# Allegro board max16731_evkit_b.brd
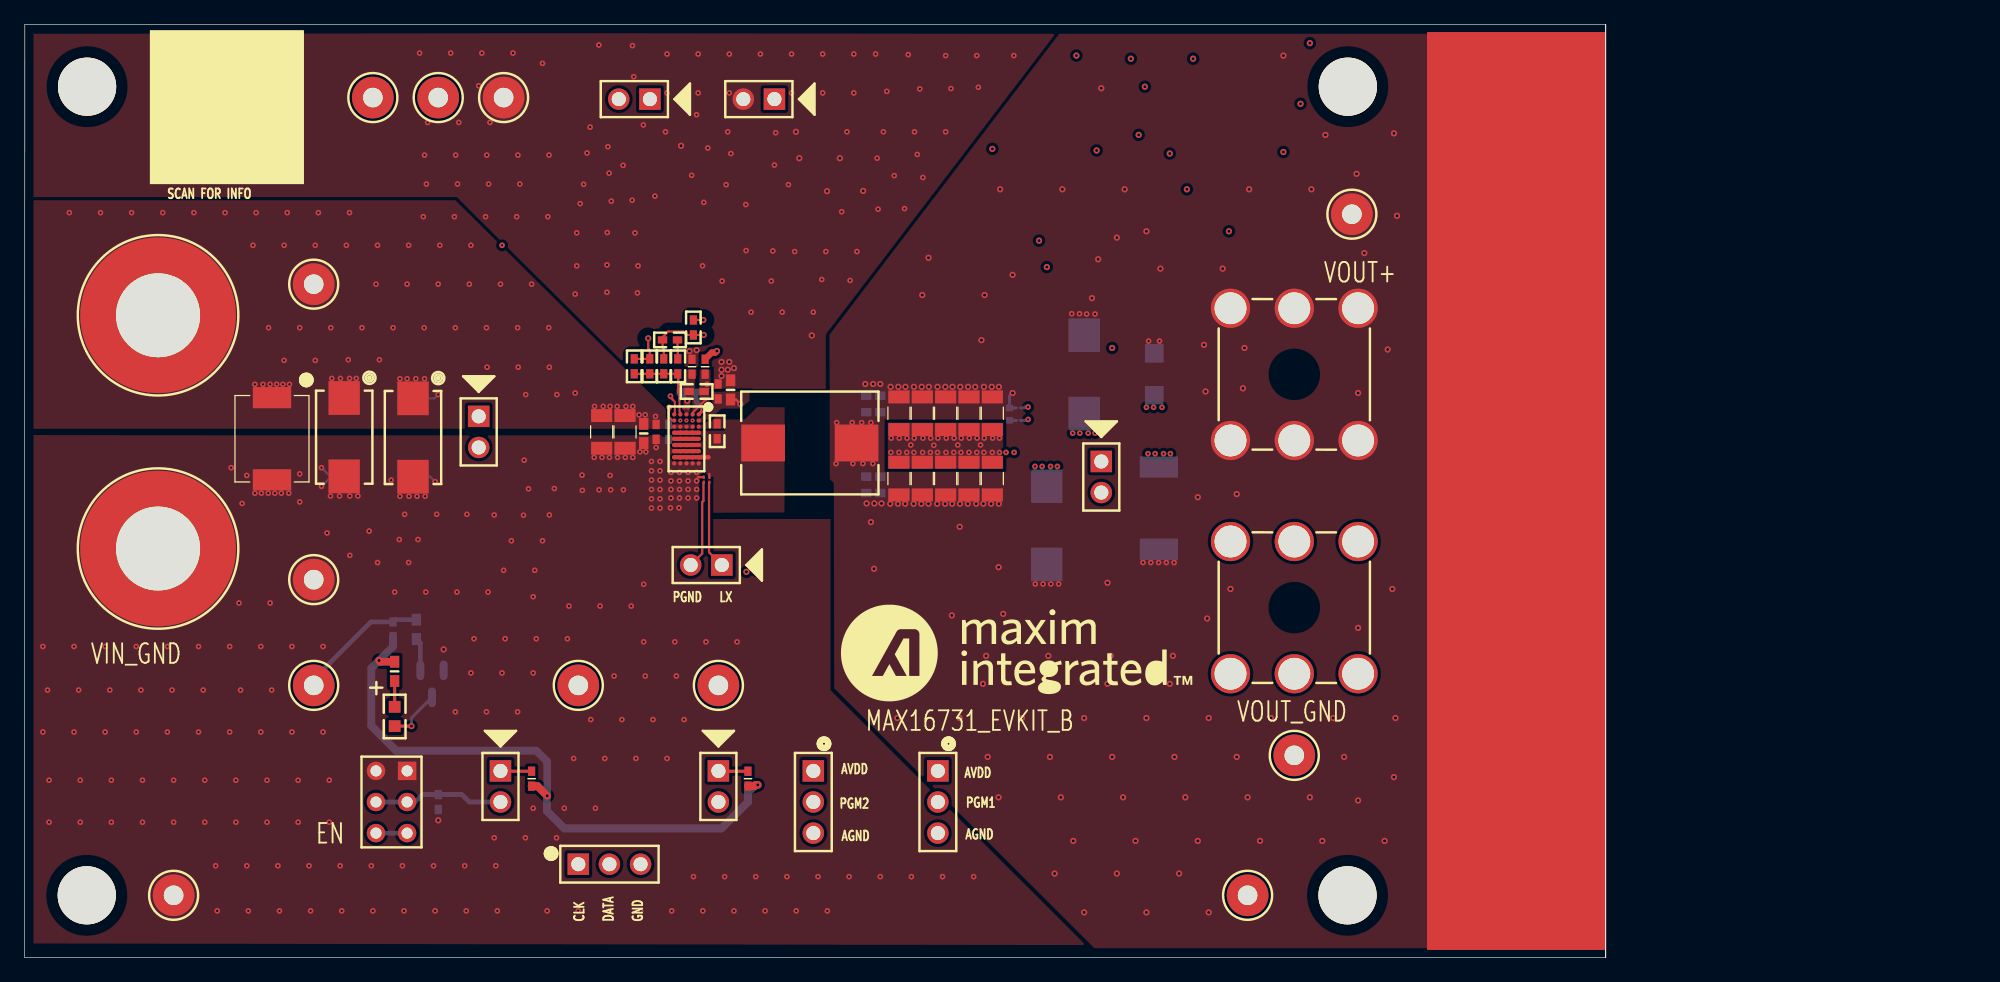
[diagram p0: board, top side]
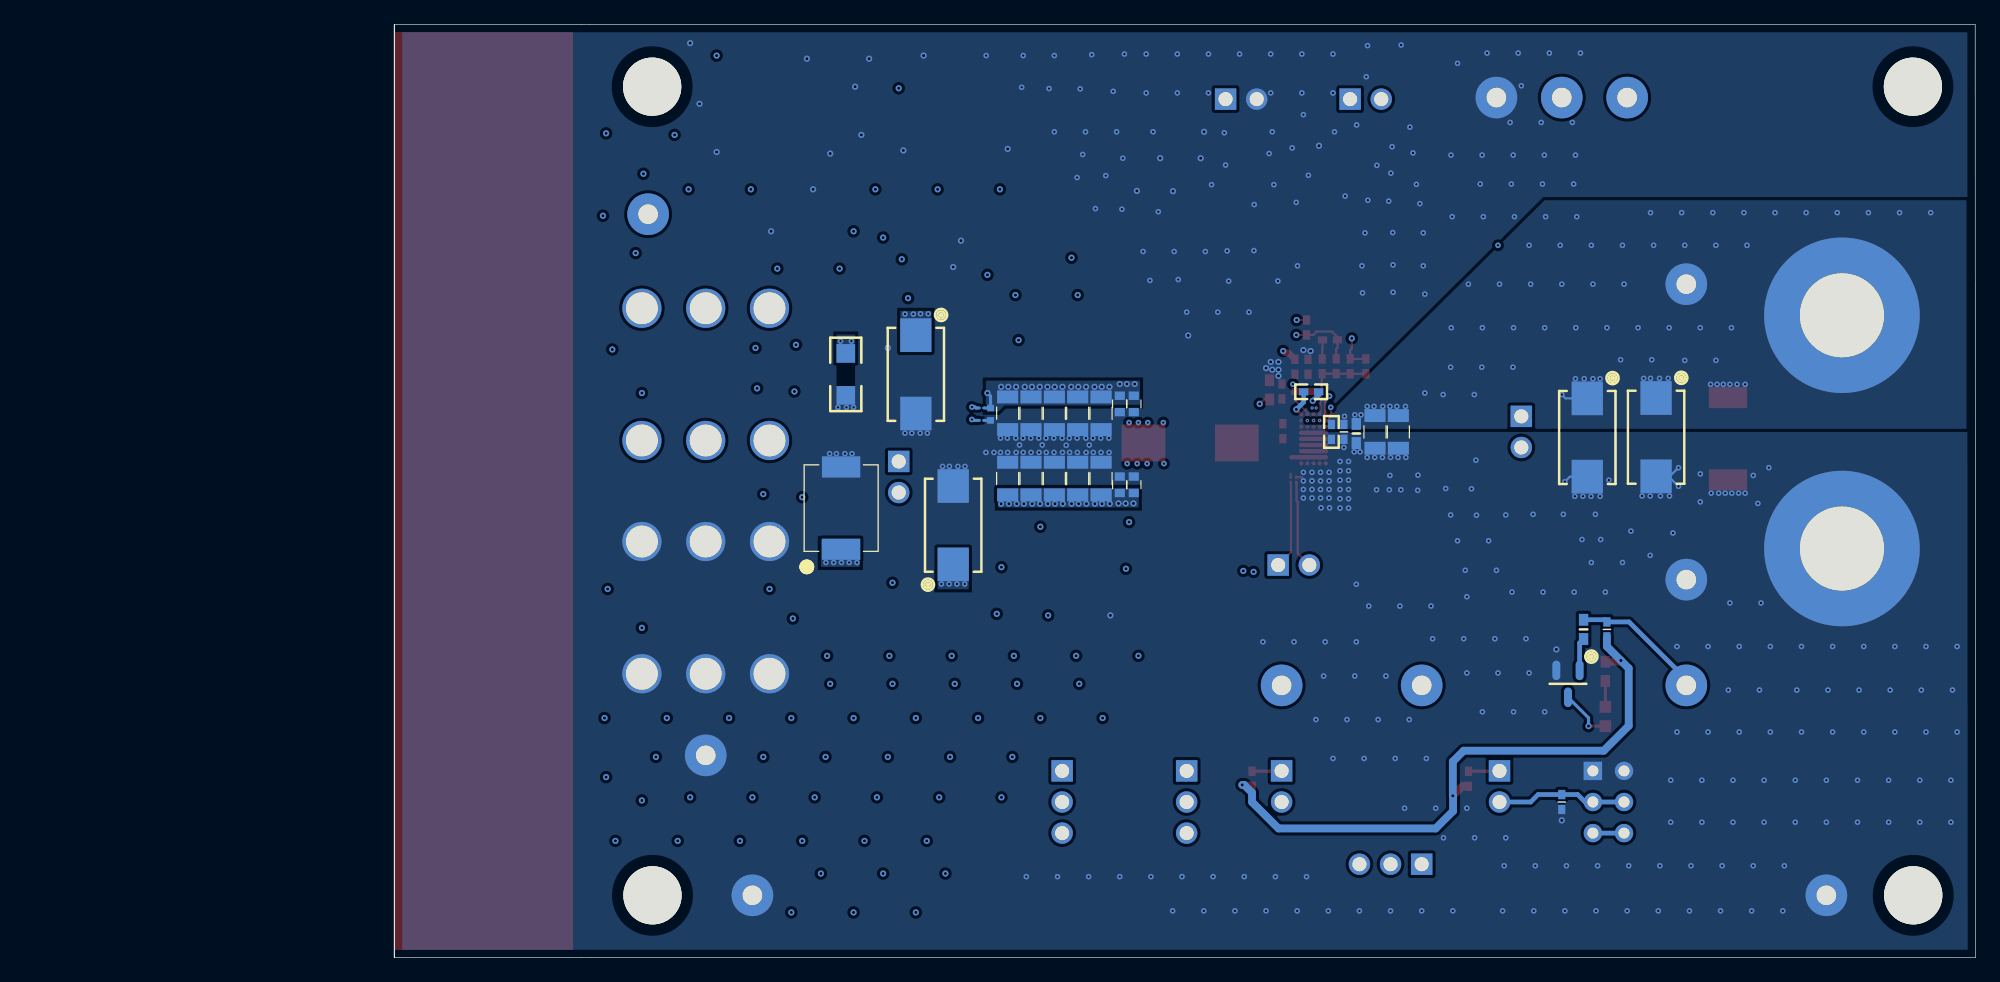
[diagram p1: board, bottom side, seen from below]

Outline 129.01 x 76.2 mm; copper layers: TOP, L2_PGND, L3_SIG_AGND, L4_SIG, L5_PGND, BOTTOM. Coordinates in mm from the lower left corner of the outline.
Outline path: 0,0 0.03,76.2 129.01,76.2 129.01,0 0,0

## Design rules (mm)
constraint set DEFAULT: min track width 0.178

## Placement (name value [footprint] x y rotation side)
C1  4.7UF  [0603]  57.61 46.36 270 top
C2  22UF  [1206]  49 42.93 90 top
C3  100UF  [1206]  78.97 39.12 270 bottom
C4  0.1UF  [0402]  56.59 46.23 270 top
C5  100UF  [1206]  73.25 39.12 270 bottom
C6  1UF  [0402]  54.84 46.23 0 top
C7  100UF  [1206]  75.16 44.45 90 bottom
C8  100UF  [1206]  73.25 44.45 90 bottom
C9  100UF  [1206]  73.25 44.45 90 top
C10  0.47UF  [0402]  56.52 42.98 90 top
C11  100UF  [1206]  73.25 39.12 270 top
C13  100UF  [1206]  71.35 44.45 90 top
C14  1UF  [0603]  50.52 42.8 90 top
C16  100UF  [1206]  71.35 39.12 270 top
C17  100PF  [0402]  49.75 48.28 270 top
C20  22UF  [1206]  47.09 42.93 90 top
C21  22UF  [1206]  49 42.93 90 bottom
C23  0.01UF  [0402]  52.67 50.44 0 top
C24  1UF  [0603]  50.52 42.8 90 bottom
C26  1000PF  [0402]  33.76 12.7 270 bottom
C27  4700PF  [0402]  52.55 42.93 90 bottom
C28  4700PF  [0402]  51.54 42.93 90 bottom
C29  0.1UF  [0402]  51.54 42.93 90 top
C30  22UF  [1206]  47.09 42.93 90 bottom
C31  470UF  [CAPMP7343X430M]  86.46 47.63 270 bottom
C32  100UF  [CAPMP7343X430M]  31.67 42.47 270 bottom
C33  100UF  [1206]  78.97 44.45 90 bottom
C34  100UF  [1206]  77.06 39.12 270 bottom
C35  100UF  [1206]  75.16 39.12 270 bottom
C36  100UF  [CAPMP7343X430M]  31.7 42.47 270 top
C37  100UF  [CAPMP7343X430M]  26.06 42.49 270 bottom
C39  100UF  [CAPMP7343X430M]  26.09 42.49 270 top
C40  470UF  [CAPMP7343X430M]  83.41 35.31 90 bottom
C41  47UF  [1206]  77.06 39.12 90 top
C43  47UF  [1206]  77.06 44.45 270 top
C44  47UF  [1206]  78.97 39.12 90 top
C46  100UF  [1206]  77.06 44.45 90 bottom
C47  0.1UF  [0402#2]  80.37 44.37 270 bottom
C48  100UF  [1206]  71.35 39.12 270 bottom
C49  47UF  [1206]  78.97 44.45 270 top
C50  100UF  [1206]  71.35 44.45 90 bottom
C51  10UF  [0603#2]  69.82 38.61 90 bottom
C52  10UF  [0603#2]  69.82 45.21 270 bottom
C53  10UF  [0603#2]  68.68 38.61 90 bottom
C54  100UF  [1206]  75.16 39.12 270 top
C55  100UF  [1206]  75.16 44.45 90 top
C72  10UF  [0603#2]  68.68 45.21 270 bottom
D1  MBRS540T3  [SOD9962X245M]  20.19 42.37 270 top
D3  MBRS540T3  [SOD9962X245M]  92.56 36.7 90 bottom
DS1  LGL29K-G2J1-24-Z  [LED_SMT160X080]  30.2 19.69 270 top
J1  PEC03SAAN  [SULLINS_PXC03SAAN]  74.52 15.24 270 top
J2  TSW-101-22-L-D  [SMTC_TSW-101-22-X-D]  61.19 70.1 90 top
J3  TSW-101-22-L-D  [SMTC_TSW-101-22-X-D]  51.03 70.1 90 top
J4  PEC03SAAN  [SULLINS_PXC03SAAN]  64.36 15.24 270 top
J5  6095  [KEYSTONE_6095]  10.9 52.45 0 top
J6  TSW-101-22-L-D  [SMTC_TSW-101-22-X-D]  38.84 15.24 180 top
J7  TSW-101-22-L-D  [SMTC_TSW-101-22-X-D]  56.62 15.24 180 top
J8  6095  [KEYSTONE_6095]  10.9 33.4 0 top
J9  PEC03SAAN  [SULLINS_PXC03SAAN]  45.19 7.62 0 top
J10  TSW-101-22-L-D  [SMTC_TSW-101-22-X-D]  37.06 44.2 180 top
J12  FINGERS_EVAL_NS  [EK_FINGERS_EVAL_NS]  121.72 38.1 90 top
J13  TSW-101-22-L-D  [SMTC_TSW-101-22-X-D]  56.9 32.05 90 top
J19  TSW-101-22-L-D  [SMTC_TSW-101-22-X-D]  87.86 40.51 180 top
L1  220NH  [IND_FP1008R5]  64.08 42.02 0 top
MH1  9032  [KEYS_9032]  5.11 71.12 180 bottom
MH2  9032  [KEYS_9032]  5.08 5.08 180 bottom
MH3  9032  [KEYS_9032]  107.98 71.12 180 bottom
MH4  9032  [KEYS_9032]  107.95 5.08 180 bottom
NOREF  -  []  0 0 90 top
NOREF#2  -  []  54.08 168.91 0 top
NOREF#3  -  []  0 0 0 top
NOREF#4  -  []  -10.69 -44.45 0 top
NOREF#5  -  []  10.23 63.16 0 top
NOREF#6  -  []  -17.04 -57.15 0 top
NOREF#7  -  []  70.59 24.77 0 top
NOREF#8  -  []  163.3 35.56 0 top
NOREF#9  -  []  -17.04 -57.15 180 bottom
Q1  BSS138  [SOT95P237X112-3M]  33.25 22.35 270 bottom
R1  4.7  [0402]  55.53 48.25 270 top
R2  95.3  [0402]  54.2 46.2 0 bottom
R4  100  [1206#2]  92.18 47.63 270 bottom
R9  3K  [0402]  51.02 48.28 90 top
R11  0  [0402]  54.47 48.25 270 top
R13  3K  [0402]  52.16 48.28 90 top
R14  10  [0402]  54.57 51.46 90 top
R16  3K  [0402]  41.38 14.61 270 top
R17  3K  [0402]  59.03 14.61 270 top
R19  0  [0402]  53.3 48.28 270 top
R41  20K  [0402]  30.07 26.8 270 bottom
R42  100  [0603]  31.98 26.8 270 bottom
R51  210  [0603]  30.2 23.37 270 top
ST1  7808  [KEYSTONE_7808]  103.61 47.63 270 top
ST2  7808  [KEYSTONE_7808]  103.61 28.58 270 top
SU3  SX1100-B  [EVKIT_SHUNT]  103.48 79.08 0 top
SW1  -  [SW_GT21MCBE]  29.95 12.7 180 top
TP1  N/A  [KEYS_5011]  39.09 70.23 0 top
TP2  N/A  [KEYS_5011]  12.17 5.08 0 top
TP4  N/A  [KEYS_5010]  23.6 54.99 0 top
TP6  N/A  [KEYS_5126]  56.62 22.23 0 top
TP7  N/A  [KEYS_5011]  23.6 30.86 0 top
TP8  N/A  [KEYS_5010]  108.31 60.71 0 top
TP9  N/A  [KEYS_5011]  99.8 5.08 90 top
TP11  N/A  [KEYS_5011]  103.61 16.51 0 top
TP13  N/A  [KEYS_5012]  28.42 70.23 90 top
TP14  N/A  [KEYS_5012]  33.76 70.23 90 top
TP29  N/A  [KEYS_5126]  45.19 22.23 90 top
TP30  N/A  [KEYS_5126]  23.6 22.23 90 top
U1  MAX16731  [MAXIM_21-100425_SMD]  54.01 42.36 270 top
Y1  CONN_SENSE_POINT  [EK_CONN_SENSE_POINT]  81.1 43.87 0 bottom
Y2  CONN_SENSE_POINT  [EK_CONN_SENSE_POINT]  81.1 44.88 0 bottom
Y12  CONN_SENSE_POINT  [EK_CONN_SENSE_POINT]  55.42 39.01 90 top
Y15  CONN_SENSE_POINT  [EK_CONN_SENSE_POINT]  55.88 39.01 90 top

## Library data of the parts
C1 = CAP_NP: alternate symbols: 0603_NOSILK,CAPC1608X90L,CAP0603-NOT_FOR_TEST; part number: CAP_NP_0603CAP-0603,4.7UF,20-004U7-R1
C2 C20 C21 C30 = CAP_NP: alternate symbols: CAPC3216X90L; part number: CAP_NP_1206CAP-1206,22UF,20-0022U-EA83
C3 C5 C7-C9 C11 C13 C16 C33-C35 C46 C48 C50 C54 C55 = CAP_NP: alternate symbols: CAPC3216X90L; part number: CAP_NP_1206CAP-1206,100UF,EC111000002982
C4 = CAP_NP: alternate symbols: 0402_NOSILK,CAPC1005X50L; part number: CAP_NP_0402CAP-0402,0.1UF,20-000U1-19A
C6 = CAP_NP: alternate symbols: 0402_NOSILK,CAPC1005X50L,CAP0402-NOT_FOR_TEST; part number: CAP_NP_0402CAP-0402,1UF,20-0001U-19A
C10 = CAP_NP: alternate symbols: 0402_NOSILK,CAPC1005X50L,CAP0402-NOT_FOR_TEST; part number: CAP_NP_0402CAP-0402,0.47UF,20-00U47-CA50
C14 C24 = CAP_NP: alternate symbols: 0603_NOSILK,CAPC1608X90L,CAP0603-NOT_FOR_TEST; part number: CAP_NP_0603CAP-0603,1UF,20-0001U-P6
C17 = CAP_NP: alternate symbols: 0402_NOSILK,CAPC1005X50L,CAP0402-NOT_FOR_TEST; part number: CAP_NP_0402CAP-0402,100PF,EC111000001552
C23 = CAP_NP: alternate symbols: 0402_NOSILK,CAPC1005X50L,CAP0402-NOT_FOR_TEST; part number: CAP_NP_0402CAP-0402,0.01UF,20-00U01-B16
C26 = CAP_NP: alternate symbols: 0402_NOSILK,CAPC1005X50L; part number: CAP_NP_0402CAP-0402,1000PF,20-1000P-E7
C27 C28 = CAP_NP: alternate symbols: 0402_NOSILK,CAPC1005X50L; part number: CAP_NP_0402CAP-0402,4700PF,20-4700P-12
C29 C47 = CAP_NP: alternate symbols: 0402_NOSILK,CAPC1005X50L,CAP0402-NOT_FOR_TEST; part number: CAP_NP_0402CAP-0402,0.1UF,20-000U1-B68
C31 C40 = CAP_POL: part number: CAP_POL_7343CAP-CAPMP7343X430M,470UF,20-0470U-N2
C32 C36 C37 C39 = CAP_POL: part number: CAP_POL_7343CAP-CAPMP7343X430M,100UF,20-0100U-I9A
C41 C43 C44 C49 = CAP_NP: alternate symbols: CAPC3216X90L; part number: CAP_NP_1206CAP-1206,47UF,ECM1107
C51-C53 C72 = CAP_NP: alternate symbols: 0603_NOSILK,CAPC1608X90L; part number: CAP_NP_0603CAP-0603,10UF,20-0010U-CA02
D1 D3 = DIO_SCHOTTKY: alternate symbols: SOD7958X245L; part number: DIO_SCHOTTKY_SMC_CASE403-03-SOD9962X245M,MBRS540T3,30-MBRS540T3-00
DS1 = LED: alternate symbols: LED_SMT160X080_ALT; part number: LED_SMT160X080-LED_SMT160X080,LGL29K-G2J1-24-Z,30-LGL29KG2J124Z-00
J1 J4 J9 = HEADER_3P: alternate symbols: SULLINS_PXC03SL; part number: HEADER_3P_TH-SULLINS_PXC03SAAN,PEC03SAAN,01-PEC03SAAN3P-21
J2 J3 J6 J7 J10 J13 J19 = HEADER_1P_X_2R: part number: HEADER_1P_X_2R_TH-SMTC_TSW-101-22-X-D,TSW-101-22-L-D,01-TSW10122LD2P-19
J5 J8 = BANANA: alternate symbols: KEYSTONE_6095_LUG_HEAD,KEYSTONE_6095_LUG_NUT; part number: BANANA_TMR1-KEYSTONE_6095,6095,01-60952P-80
J12 = EK_FINGERS_EVAL_NS: part number: EK_FINGERS_EVAL_NS_EDGE-EK_FINGERS_EVAL_NS,FINGERS_EVAL_NS,N/A
L1 = INDUCT: part number: INDUCT_SMT-IND_FP1008R5,220NH,EL111000005364
MH1-MH4 = SPACER: part number: SPACER_MECH-02-SOM35016H-00,9032,KEYS_9032
Q1 = TRAN_NCH_3P: part number: TRAN_NCH_3P_SOT23-SOT95P237X112-3M,BSS138,90-BSS138-16
R1 = RES: alternate symbols: (0402_NOSILK,RESC1005X50L); part number: RES_0402RES-0402,4.7,80-004R7-23
R2 = RES: alternate symbols: (0402_NOSILK,RESC1005X50L); part number: RES_0402RES-0402,95.3,80-095R3-23
R4 = RES: part number: RES_1206RES-1206,100,80-0100R-Q5B
R9 R13 R16 R17 = RES: alternate symbols: (0402_NOSILK,RESC1005X50L); part number: RES_0402RES-0402,3K,80-0003K-23
R11 R19 = RES: alternate symbols: 0402_NOSILK,RESC1005X50L,RES0402-NOT_FOR_TEST; part number: RES_0402RES-0402,0,80-0000R-26B
R14 = RES: alternate symbols: 0402_NOSILK,RESC1005X50L,RES0402-NOT_FOR_TEST; part number: RES_0402RES-0402,10,80-0010R-23
R41 = RES: alternate symbols: 0402_NOSILK,RESC1005X50L,RES0402-NOT_FOR_TEST; part number: RES_0402RES-0402,20K,80-0020K-23
R42 = RES: alternate symbols: 0603_NOSILK,RESC1608X90L; part number: RES_0603RES-0603,100,80-0100R-24
R51 = RES: alternate symbols: (0603_NOSILK); part number: RES_0603RES-0603,210,80-0210R-24
ST1 ST2 = 7808: part number: 7808_CON-KEYSTONE_7808,7808,02-TTVER7808-00
SU3 = SHUNT: part number: SHUNT_SHUNT_2P-02-JMPFS1100B-00,SX1100-B,EVKIT_SHUNT
SW1 = GT21MCBE_TH-SW_GT21MCBE,GT21MCBE,11-GT21MCBE-00-GT21MCBE,SW_GT21MCBE
TP1 TP2 TP7 TP9 TP11 = TP: alternate symbols: TP_C340H160L; part number: TP_TP-KEYS_5011,N/A,02-TPMINI5011-00
TP4 TP8 = TP: alternate symbols: TP_C340H160L;KEYS_5010L; part number: TP_TP-KEYS_5010,N/A,02-TPMINI5010-00
TP6 TP29 TP30 = TP: part number: TP_TP-KEYS_5126,N/A,02-TPMULTI5126-00
TP13 TP14 = TP: part number: TP_TP-KEYS_5012,N/A,02-TPMINI5012-00
U1 = EK_MAX16731: part number: EK_MAX16731_WLP45-MAXIM_21-100425_SMD,MAX16731,N/A
Y1 Y2 Y12 Y15 = EK_CONN_SENSE_POINT: part number: EK_CONN_SENSE_POINT_SMD-EK_CONN_SENSE_POINT,CONN_SENSE_POINT,N/A

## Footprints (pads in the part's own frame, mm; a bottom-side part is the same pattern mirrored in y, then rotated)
0402
  rect 0.762x0.584 smd: 1(-0.61,0) 2(0.61,0)
0402#2
  rect 0.533x0.559 smd: 1(-0.508,0) 2(0.508,0)
0603
  rect 0.965x0.762 smd: 1(-0.787,0) 2(0.787,0)
0603#2
  rect 0.69x0.83 smd: 1(-0.67,0) 2(0.67,0)
1206
  rect 1.05x1.72 smd: 1(-1.335,0) 2(1.335,0)
1206#2
  rect 1.524x1.524 smd: 1(-1.714,0) 2(1.714,0)
CAPMP7343X430M
  rect 2.75x2.55 smd: 1(-3.2,0) 2(3.2,0)
EK_CONN_SENSE_POINT
  custom 0.04x0.04 smd: 1(-0.216,0) 2(0.216,0)
EK_FINGERS_EVAL_NS
  rect 74.93x14.567 smd: 1(0,0) 2(0,0)
IND_FP1008R5
  rect 3.56x3 smd: 1(-3.81,0) 2(3.81,0)
KEYS_5010
  round 3.4 hole 1.6: 1(0,0)
KEYS_5011
  round 3.4 hole 1.6: 1(0,0)
KEYS_5012
  round 3.4 hole 1.6: 1(0,0)
KEYS_5126
  round 3.4 hole 1.6: 1(0,0)
KEYS_9032
  round 4.75 hole 4.75 unplated: (0,0)
KEYSTONE_6095
  round 12.7 hole 6.858: 1(0,0)
KEYSTONE_7808
  round 3.2 hole 2.6: 1(-5.4,5.205) 2(-5.4,0) 3(-5.4,-5.205) 4(5.4,5.205) 5(5.4,0) 6(5.4,-5.205)
LED_SMT160X080
  rect 0.96x0.96 smd: A(-0.787,0) K(0.787,0)
MAXIM_21-100425_SMD
  round 0.348 smd: A1(-2,1) A2(-1.5,1) A3(-1,1) A4(-0.5,1) A5(0,1) A6(0.5,1) A7(1,1) A8(1.5,1) A9(2,1) B1(-2,0.5) B2(-1.5,0.5) B3(-1,0.5) B4(-0.5,0.5) B5(0,0.5) B6(0.5,0.5) B7(1,0.5) B8(1.5,0.5) B9(2,0.5) C1(-2,0) C2(-1.5,0) C3(-1,0) C4(-0.5,0) C5(0,0) C6(0.5,0) C7(1,0) C8(1.5,0) C9(2,0) D1(-2,-0.5) D2(-1.5,-0.5) D3(-1,-0.5) D4(-0.5,-0.5) D5(0,-0.5) D6(0.5,-0.5) D7(1,-0.5) D8(1.5,-0.5) D9(2,-0.5) E1(-2,-1) E2(-1.5,-1) E3(-1,-1) E4(-0.5,-1) E5(0,-1) E6(0.5,-1) E7(1,-1) E8(1.5,-1) E9(2,-1)
SMTC_TSW-101-22-X-D
  rect 1.75x1.75 hole 1.15: 1(0,0)
  round 1.75 hole 1.15: 2(0,2.54)
SOD9962X245M
  rect 1.73x3.13 smd: A(3.36,0) C(-3.36,0)
SOT95P237X112-3M
  oval 1.6x0.65 smd: 1(-1.1,0.95) 2(-1.1,-0.95) 3(1.1,0)
SULLINS_PXC03SAAN
  rect 1.75x1.75 hole 1.15: 1(0,0)
  round 1.75 hole 1.15: 2(2.54,0) 3(5.08,0)
SW_GT21MCBE
  rect 1.5x1.5 hole 0.9: 1(-1.27,-2.54)
  round 1.5 hole 0.9: 2(-1.27,0) 3(-1.27,2.54) 4(1.27,-2.54) 5(1.27,0) 6(1.27,2.54)

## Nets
1.8V_VCC: C1.2 C4.2 J2.1 R1.1 R16.2 R17.2 R41.2 R51.1 U1.A2
AVDD: C6.2 J1.1 J3.1 J4.1 R1.2 U1.B1
GND_POWER: C1.1 C2.1 C3.1 C4.1 C5.1 C7.1 C8.1 C9.1 C11.1 C13.1 C14.1 C16.1 C20.1 C21.1 C24.1 C26.2 C27.1 C28.1 C29.1 C30.1 C31.2(B) C32.2(B) C33.1 C34.1 C35.1 C36.2(B) C37.2(B) C39.2(B) C40.2(B) C41.2 C43.2 C44.2 C46.1 C47.2 C48.1 C49.2 C50.1 C51.2 C52.2 C53.2 C54.1 C55.1 C72.2 D1.A D3.A J2.2 J8.1(P) J10.2 J12.2 J19.2 Q1.2(S) R4.2 R11.1 ST2.1 ST2.2 ST2.3 ST2.4 ST2.5 ST2.6 SW1.1 SW1.4 TP1.1(TP1) TP2.1(TP1) TP7.1(TP1) TP9.1(TP1) TP11.1(TP1) U1.A5 U1.A7 U1.A9 U1.B5 U1.B7 U1.B9 U1.C5 U1.C7 U1.C9 U1.D5 U1.D7 U1.D9 U1.E5 U1.E7 U1.E9 Y1.1 Y12.2(P2)
GND_SIGNAL: C6.1 J1.3 J3.2 J4.3 J9.3 R2.1 R11.2 U1.C1
VDDH: C2.2 C14.2 C20.2 C21.2 C24.2 C27.2 C28.2 C29.2 C30.2 C32.1 C36.1 C37.1 C39.1 D1.C(K) J5.1(P) J10.1 TP4.1(TP1) U1.B3 U1.C3 U1.D3 U1.E3
EN: J6.1 J9.1 R16.1 TP29.1(TP1) U1.E2
LX: C10.1 L1.1 U1.A4 U1.A6 U1.A8 U1.B4 U1.B6 U1.B8 U1.C4 U1.C6 U1.C8 U1.D4 U1.D6 U1.D8 U1.E4 U1.E6 U1.E8 Y15.2(P2)
PGM0: R2.2 U1.A1
PGM1: J1.2 U1.B2
PGM2: J4.2 J7.2 J9.2 U1.C2
PGOOD: R41.1 R42.1 TP30.1(TP1) U1.E1
UNNAMED_1_CAPNP_I109_1: C23.1 R13.2 R14.1 TP13.1(TP1)
UNNAMED_1_CAPNP_I109_2: C23.2 R19.1
UNNAMED_1_CAPNP_I259_2: C17.2 R9.1 R13.1 R19.2 U1.D1
UNNAMED_1_CAPNP_I293_2: C10.2 U1.A3
UNNAMED_1_EKCONNSENSEPOINT_I310_P1: J13.2 Y12.1
UNNAMED_1_EKCONNSENSEPOINT_I311_P1: J13.1 Y15.1
UNNAMED_4_CAPNP_I188_1: C26.1 J6.2 SW1.2 SW1.5
UNNAMED_4_GT21MCBE_I190_3: SW1.3 SW1.6
UNNAMED_4_HEADER1PX2R_I239_1: J7.1 R17.1 TP6.1(TP1)
UNNAMED_4_LED_I206_A: DS1.A R51.2
UNNAMED_4_LED_I206_B: DS1.K(B) Q1.3
UNNAMED_4_RESSMD_I203_2: Q1.1 R42.2
VOUT: C3.2 C5.2 C7.2 C8.2 C9.2 C11.2 C13.2 C16.2 C31.1 C33.2 C34.2 C35.2 C40.1 C41.1 C43.1 C44.1 C46.2 C47.1 C48.2 C49.1 C50.2 C51.1 C52.1 C53.1 C54.2 C55.2 C72.1 D3.C(K) J12.1 J19.1 L1.2 R4.1 ST1.1 ST1.2 ST1.3 ST1.4 ST1.5 ST1.6 TP8.1(TP1) Y2.1
VOUT_HF_CAP_N: C17.1 R9.2 U1.D2 Y1.2(P2)
VOUT_HF_CAP_P: R14.2 TP14.1(TP1) Y2.2(P2)

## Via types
v1: diameter 0.508, hole 0.254, TOP to BOTTOM, 172 vias
v2: diameter 0.457, hole 0.203, TOP to BOTTOM, 470 vias
v3: diameter 0.254, hole 0.127, TOP to BOTTOM, 5 vias

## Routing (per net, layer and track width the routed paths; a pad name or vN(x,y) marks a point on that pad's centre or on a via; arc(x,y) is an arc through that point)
1.8V_VCC: length 122.2
  TOP w0.178: v1(58.4,45.22) 58.05,45.57 C1.2
  TOP w0.508: v1(56.49,49.53) 56.36,49.4 56.08,49.4 R1.1
  TOP w0.635: v1(42.65,13.21) 41.86,14 R16.2 ; v1(59.83,14.1) 59.66,14.1 59.56,14 R17.2 ; v1(28.93,24.26) 29.03,24.16 R51.1
  L3_SIG_AGND w0.178: J2.1 60.02,68.94 60.02,63.91 63.93,60 63.93,53.47 63.5,53.04 63.5,51.03 58.4,45.94 v1(58.4,45.22)
  L4_SIG w0.635: v1(56.49,49.53) 56.55,49.47 57.85,49.47 58.71,48.6 58.71,47.33 58.4,47.03 v1(58.4,45.22) 62.08,41.54 62.08,19.3 59.83,17.06 v1(59.83,14.1)
  BOTTOM w0.635: R41.2 30.07,25.4 v1(28.93,24.26) 28.3,23.62 28.3,18.92 30.33,16.89 41.76,16.89 42.65,16 v1(42.65,13.21) 42.62,13.19 42.62,11.96 44.04,10.54 56.87,10.54 59.03,12.7 59.03,13.46 59.66,14.1 v1(59.83,14.1)
AVDD: length 86.9
  TOP w0.152: U1.B1 54.51,44.5 55.55,45.54 55.63,45.54
  L3_SIG_AGND w0.178: J3.1 49.91,68.99 49.91,66.73 51.51,65.14 56.71,65.14 60.27,61.58 60.27,52.29 58.11,50.13 56.24,50.13 55.89,49.78 55.89,48.72 55.6,48.43 55.6,46.91 v2(55.69,46.82)
  L3_SIG_AGND w0.254: J1.1 71.98,15.24 63.93,23.29 63.93,37.08 57.43,43.59 57.43,45.08 v2(55.69,46.82)
  L4_SIG w0.381: J4.1 J1.1
GND_POWER: length 75.9
  TOP w0.178: Y12.2 54.93,39.23
  TOP w0.348: U1.A5 U1.B5 U1.C5 U1.D5 U1.E5 ; U1.E7 U1.D7 U1.C7 U1.B7 U1.A7
  L3_SIG_AGND w0.178: v1(57.89,48.13) 57.89,47.38 58.06,47.2 59.07,47.2 63.03,51.16 63.03,53.23 63.51,53.71 63.51,59.83 59.6,63.74 59.6,69.15 J2.2
  L4_SIG w0.178: v2(51.54,41.66) 51.16,41.66 50.3,42.51 38.16,42.51 38.12,42.55 37.95,42.55 J10.2 ; J19.2 86.46,37.97 85.83,38.61 82.55,38.61 81.38,39.77 81.38,42.04 79.98,43.43 70.95,43.43 70.71,43.2 v2(70.71,42.42)
  BOTTOM w0.178: C32.2 33.1,39.27 v2(33.5,38.86) ; 25.04,39.29 C37.2 ; 25.04,39.29 24.94,39.29 v2(24.23,40.01) ; 25.04,39.29 v2(24.23,38.48)
  BOTTOM w0.254: Y1.1 C47.2
  vias: v1(33.76,11.2) v1(34.2,25.16) v1(53.57,66.29) v1(54.25,49.53) v1(54.84,49.61) v1(56.87,48.64) v1(56.87,48.01) v1(56.87,47.5) v1(57.38,48.01) v1(57.51,48.64) v1(62.94,67.44) v1(63.22,65.28) v1(64.24,50.8) v1(65.48,62.59) v1(66.52,65.28) v1(68.43,62.61) v1(70.59,27.94) v1(78.97,66.04) v1(82.78,58.55) v1(83.41,56.39) v1(85.83,73.66) v1(87.48,65.91) v1(88.75,49.78) v1(90.27,73.41) v1(90.91,67.18) v1(91.41,71.12) v1(93.45,65.66) v1(94.84,62.74) v1(95.35,73.41) v1(98.27,59.31) v1(102.72,65.79) v1(104.11,69.72) v1(104.88,74.68) v2(1.5,25.4) v2(1.5,18.42) v2(1.88,21.84) v2(2.01,14.48) v2(2.01,11.05) v2(4.04,25.4) v2(4.04,18.42) v2(4.42,21.84) v2(4.55,14.48) v2(4.55,11.05) v2(6.58,25.4) v2(6.58,18.42) v2(6.96,21.84) v2(7.09,14.48) v2(7.09,11.05) v2(9.12,25.4) v2(9.12,18.42) v2(9.5,21.84) v2(9.63,14.48) v2(9.63,11.05) v2(11.66,25.4) v2(11.66,18.42) v2(12.04,21.84) v2(12.17,14.48) v2(12.17,11.05) v2(14.2,25.4) v2(14.2,18.42) v2(14.58,21.84) v2(14.71,14.48) v2(14.71,11.05) v2(15.6,7.49) v2(15.72,3.81) v2(16.74,25.4) v2(16.74,18.42) v2(16.87,40.01) v2(17.25,14.48) v2(17.25,11.05) v2(17.5,28.96) v2(17.63,21.84) v2(17.75,37.08) v2(18.14,39.37) v2(18.14,7.49) v2(18.26,3.81) v2(18.8,37.92) v2(19.33,37.92) v2(19.28,25.4) v2(19.28,18.42) v2(19.79,14.48) v2(19.79,11.05) v2(19.89,37.92) v2(20.04,28.96) v2(20.17,21.84) v2(20.42,37.92) v2(20.68,7.49) v2(20.8,3.81) v2(20.95,37.92) v2(21.56,37.92) v2(21.82,25.4) v2(21.82,18.42) v2(22.33,14.48) v2(22.33,11.05) v2(22.45,39.5) v2(22.45,37.21) v2(23.22,7.49) v2(23.34,3.81) v2(24.36,25.4) v2(24.36,18.42) v2(24.69,34.67) v2(24.87,14.48) v2(24.87,11.05) v2(24.97,37.69) v2(25.7,37.69) v2(25.76,7.49) v2(25.88,3.81) v2(26.54,37.69) v2(26.54,32.84) v2(27.2,37.69) v2(28.12,34.82) v2(28.3,7.49) v2(28.42,3.81) v2(28.8,32.26) v2(29.92,38.99) v2(30.2,29.85) v2(30.63,37.67) v2(30.58,34.14) v2(30.84,7.49) v2(31.01,36.2) v2(30.96,3.81) v2(31.34,32.26) v2(31.37,37.67) v2(32.03,37.67) v2(32.11,34.14) v2(32.23,73.86) v2(32.64,65.53) v2(32.69,37.67) v2(32.74,29.85) v2(32.79,63.17) v2(32.89,68.2) v2(33.38,7.49) v2(33.5,3.81) v2(33.63,36.2) v2(34.77,73.86) v2(35.15,20.07) v2(35.18,65.53) v2(35.33,63.17) v2(35.28,29.85) v2(35.43,68.2) v2(35.92,7.49) v2(36.04,3.81) v2(36.09,36.2) v2(36.42,23.24) v2(36.68,26.04) v2(37.06,71.2) v2(37.31,73.86) v2(37.62,60.5) v2(37.72,65.53) v2(37.69,20.07) v2(37.82,29.85) v2(37.87,63.17) v2(37.97,68.2) v2(38.33,36.14) v2(38.33,9.78) v2(38.46,7.49) v2(38.58,3.81) v2(38.96,58.17) v2(38.96,23.24) v2(39.09,31.62) v2(39.22,26.04) v2(39.73,34.04) v2(39.85,73.86) v2(40.16,60.5) v2(40.23,20.07) v2(40.26,65.53) v2(40.41,63.17) v2(40.72,36.12) v2(40.77,40.61) v2(40.87,9.78) v2(41.12,38.28) v2(41.5,29.46) v2(41.5,23.24) v2(41.5,12.19) v2(41.63,31.62) v2(41.76,26.04) v2(42.27,73.03) v2(42.27,34.04) v2(42.65,3.81) v2(42.7,60.5) v2(42.8,65.53) v2(42.82,36.14) v2(43.23,38.3) v2(43.41,9.78) v2(44.04,12.19) v2(44.3,26.04) v2(44.42,28.7) v2(44.81,16.26) v2(44.93,54.18) v2(45.06,59.18) v2(45.06,56.49) v2(45.19,3.81) v2(45.34,61.57) v2(45.49,39.4) v2(45.52,38.15) v2(45.62,63.14) v2(45.9,65.71) v2(46.15,67.82) v2(46.2,19.43) v2(46.48,40.84) v2(46.58,12.19) v2(46.86,74.52) v2(46.89,38.2) v2(46.96,28.7) v2(47.12,40.84) v2(47.35,16.26) v2(47.55,59.21) v2(47.52,56.57) v2(47.52,54.33) v2(47.6,66.22) v2(47.7,64.06) v2(47.73,40.84) v2(47.73,3.81) v2(47.78,39.37) v2(47.83,38.2) v2(47.88,61.77) v2(48.11,22.99) v2(48.39,40.84) v2(48.74,19.43) v2(48.84,64.69) v2(48.87,38.2) v2(49.02,40.84) v2(49.5,28.7) v2(49.61,74.47) v2(49.58,61.85) v2(49.63,40.84) v2(49.71,71.93) v2(49.81,59.18) v2(49.89,16.26) v2(50.01,54.28) v2(50.06,56.49) v2(50.22,41.3) v2(50.27,3.81) v2(50.5,68) v2(50.52,30.48) v2(50.52,25.78) v2(50.65,22.99) v2(50.7,41.3) v2(51.16,40.51) v2(51.16,39.75) v2(51.16,38.99) v2(51.16,38.23) v2(51.16,37.47) v2(51.16,36.7) v2(51.28,19.43) v2(51.44,62.18) v2(51.85,40.51) v2(51.85,39.75) v2(51.85,38.99) v2(51.85,38.23) v2(51.85,37.47) v2(51.85,36.7) v2(52.3,67.44) v2(52.43,73.79) v2(52.43,70.61) v2(52.43,16.26) v2(52.74,39.62) v2(52.74,38.93) v2(52.74,38.23) v2(52.74,37.53) v2(52.7,36.73) v2(52.81,3.81) v2(53.06,25.78) v2(53.19,22.99) v2(53.44,39.62) v2(53.44,38.93) v2(53.44,38.23) v2(53.44,37.53) v2(53.4,36.73) v2(53.82,19.43) v2(54.14,39.62) v2(54.14,38.93) v2(54.14,38.23) v2(54.14,37.53) v2(54.43,63.88) v2(54.58,6.6) v2(54.84,68.83) v2(54.84,39.62) v2(54.84,38.93) v2(54.84,38.23) v2(54.84,37.53) v2(54.97,73.79) v2(54.97,70.61) v2(55.32,56.49) v2(55.35,3.81) v2(55.42,61.67) v2(55.6,25.78) v2(55.75,66.12) v2(56.92,55.25) v2(57.12,6.6) v2(57.25,63.12) v2(57.38,67.44) v2(57.51,73.79) v2(57.51,70.61) v2(57.63,65.66) v2(57.89,3.81) v2(58.14,25.78) v2(58.85,61.49) v2(58.88,57.73) v2(59.28,52.71) v2(59.66,6.6) v2(60.05,73.79) v2(60.43,3.81) v2(60.93,55.25) v2(61.06,57.71) v2(61.19,64.72) v2(61.29,67.36) v2(61.82,52.71) v2(62.2,6.6) v2(62.33,63.12) v2(62.59,73.79) v2(62.59,70.61) v2(62.84,57.66) v2(62.97,3.81) v2(64.36,52.71) v2(64.74,6.6) v2(65.05,55.37) v2(65.13,73.79) v2(65.13,70.61) v2(65.38,57.66) v2(65.51,3.81) v2(66.67,60.91) v2(67.11,67.44) v2(67.28,6.6) v2(67.36,55.3) v2(67.67,73.79) v2(67.67,70.61) v2(67.92,57.66) v2(69.44,73.79) v2(69.57,65.28) v2(69.65,61.11) v2(69.82,6.6) v2(70.08,67.44) v2(70.36,70.74) v2(70.69,41.25) v2(70.97,63.86) v2(71.35,41.25) v2(71.37,42.42) v2(71.81,61.16) v2(72.01,42.42) v2(71.98,41.25) v2(72.11,73.74) v2(72.31,41.86) v2(72.36,6.6) v2(72.62,67.44) v2(72.59,42.42) v2(72.57,41.25) v2(72.85,65.58) v2(73.05,70.94) v2(73.3,63.7) v2(73.3,42.42) v2(73.28,41.25) v2(73.94,42.42) v2(73.91,41.25) v2(74.19,41.83) v2(74.52,42.42) v2(74.5,41.25) v2(74.9,6.6) v2(75.16,73.66) v2(75.16,67.44) v2(75.21,42.42) v2(75.18,41.25) v2(75.59,70.97) v2(75.84,42.42) v2(75.82,41.25) v2(76.15,41.86) v2(76.43,42.42) v2(76.4,41.25) v2(77.09,42.42) v2(77.06,41.25) v2(77.44,6.6) v2(77.7,73.66) v2(77.72,42.42) v2(77.7,41.25) v2(77.83,71.07) v2(78,41.86) v2(78.31,42.42) v2(78.28,41.25) v2(78.99,42.42) v2(78.97,41.25) v2(79.55,42.42) v2(79.55,41.25) v2(80.09,41.25) v2(80.72,73.66) v2(80.75,41.25) v2(82.45,40.11) v2(83.03,40.11) v2(83.72,40.11) v2(84.28,40.11) v2(85.52,42.82) v2(86.11,42.82) v2(86.79,42.82) v2(87.35,42.82) v2(91.54,44.93) v2(91.67,41.15) v2(92.13,44.93) v2(92.25,41.15) v2(92.81,44.93) v2(92.94,41.15) v2(93.5,41.15)
GND_SIGNAL: length 107.8
  L3_SIG_AGND w0.178: J3.2 49.49,69.1 49.49,66.56 51.33,64.72 56.54,64.72 59.86,61.4 59.86,52.47 57.93,50.55 56.07,50.55 55.47,49.95 55.47,48.89 55.09,48.51 55.09,46.36
  L3_SIG_AGND w0.635: 46.34,46.9 43.03,46.9 42.01,45.89 42.01,38.09 43.62,36.48 43.62,34.38 43.07,33.82 43.07,23.67 42.93,23.53 42.93,19.4 50.27,12.07 J9.3 54.08,7.62 56.62,10.16 J4.3 J1.3
  BOTTOM w0.381: v1(54.08,45.47) 53.59,45.95 R2.1
  vias: v3(53.8,44.88) v3(54.13,44.88)
VDDH: length 17.7
  L4_SIG w0.178: J10.1 38.33,42.93 50.14,42.93 51.41,44.2 v2(51.49,44.2)
  BOTTOM w0.178: v2(33.76,45.97) 33.45,45.67 C32.1
  vias: v2(3.66,60.83) v2(6.2,60.83) v2(8.74,60.83) v2(11.28,60.83) v2(13.82,60.83) v2(16.36,60.83) v2(18.64,58.17) v2(18.8,46.81) v2(18.9,60.83) v2(19.46,46.81) v2(19.91,51.44) v2(20.04,46.81) v2(20.57,46.81) v2(21.08,46.81) v2(21.18,58.17) v2(21.18,48.77) v2(21.44,60.83) v2(21.62,46.81) v2(22.45,51.44) v2(23.72,58.17) v2(23.72,48.77) v2(23.98,60.83) v2(24.99,51.44) v2(25.07,47.29) v2(25.78,47.29) v2(26.26,58.17) v2(26.42,48.82) v2(26.52,60.83) v2(26.52,47.29) v2(27.08,47.29) v2(27.53,51.44) v2(28.68,54.99) v2(28.8,58.17) v2(28.96,48.82) v2(30.07,51.44) v2(30.63,47.27) v2(31.22,54.99) v2(31.22,47.27) v2(31.34,58.17) v2(31.93,47.27) v2(32.54,60.5) v2(32.61,51.44) v2(32.64,47.27) v2(33.76,54.99) v2(33.88,58.17) v2(35.08,60.5) v2(35.15,51.44) v2(36.3,54.99) v2(36.42,58.17) v2(37.69,51.44) v2(37.74,48.21) v2(38.84,54.99) v2(40.23,51.44) v2(40.28,48.21) v2(40.89,45.97) v2(41.38,54.99) v2(42.77,51.44) v2(42.82,48.21) v2(43.43,45.97) v2(44.93,46.1) v2(46.51,45.01) v2(47.22,45.01) v2(47.78,45.01) v2(48.36,45.01) v2(49.07,45.01) v2(49.63,45.01) v2(50.14,44.32) v2(50.65,44.32)
EN: length 53.1
  TOP w0.152: v2(52.61,44.93) 52.61,44.59 52.56,44.54 52.56,44.17 52.87,43.86 U1.E2
  TOP w0.254: R16.1 38.9,15.21 arc(38.86,15.22) J6.1
  L4_SIG w0.254: v2(52.61,44.93) 52.98,44.56 52.98,43.39 55.89,40.48 55.89,36.66 52.45,33.22 52.45,29.49 TP29.1 44.55,22.23 38.84,16.51 J6.1 39.65,15.24 45.19,9.7 J9.1
LX: length 7.1
  TOP w0.178: Y15.2 55.88,39.5
  TOP w0.348: U1.E4 U1.D4 U1.C4 U1.B4 U1.A4 ; 55.8,40.86 55.8,40.86 U1.A8 U1.B8 U1.C8 U1.D8 U1.E8 ; U1.A6 U1.B6 U1.C6 U1.D6 U1.E6
PGM0: length 2.3
  TOP w0.254: U1.A1 v1(55.42,44.76)
  BOTTOM w0.381: v1(55.42,44.76) 54.81,45.36 R2.2
PGM1: length 40.6
  L3_SIG_AGND w0.254: v1(59.74,31.57) 61.7,29.62 61.7,23.5 71.22,13.97 73.25,13.97 J1.2
  L4_SIG w0.254: v3(54.51,43.86) 59.74,38.63 v1(59.74,31.57)
PGM2: length 55.5
  L3_SIG_AGND w0.254: J7.2 61.19,17.27 61.19,29.21 v1(58.9,31.5)
  L4_SIG w0.254: J4.2 J7.2 51.54,12.7 47.73,8.89 J9.2 ; v3(54.01,43.86) 54.01,43.35 58.9,38.46 v1(58.9,31.5)
PGOOD: length 60.9
  TOP w0.152: U1.E1 53.06,44.41 53.06,45.39 52.91,45.54
  TOP w0.203: v2(52.7,45.85) 52.7,45.75 52.91,45.54
  L4_SIG w0.203: v2(52.7,45.85) 52.18,45.33 52.18,45.32 52.04,45.17 52.04,44.7 52.3,44.43 52.3,42.99 55.42,39.87 55.42,37.29 53.2,35.06 46.25,35.06 38.11,26.92 28.3,26.92 TP30.1
  BOTTOM w0.381: R42.1 30.25,27.58 R41.1 28.27,27.41 24.23,23.37 24.23,22.86 TP30.1
UNNAMED_1_CAPNP_I109_1: length 55.7
  TOP w0.178: R13.2 52.16,49.7 52.06,49.8 C23.1 52.06,50.67 52.52,51.13 53.75,51.13 54.03,50.85 R14.1 v1(55.41,50.85)
  L3_SIG_AGND w0.178: TP13.1 29.95,70.23 30.84,71.12 30.84,72.01 31.72,72.9 41,72.9 42.65,71.25 42.65,67.94 47.42,63.17 55.8,63.17 58.14,60.83 58.14,52.32 57.38,51.56 55.98,51.56 55.41,50.99 v1(55.41,50.85)
UNNAMED_1_CAPNP_I109_2: length 1.6
  TOP w0.178: C23.2 53.28,49.8 53.3,49.78 R19.1
UNNAMED_1_CAPNP_I259_2: length 7.1
  TOP w0.152: 53.44,45.54 53.44,44.58 53.51,44.51 U1.D1
  TOP w0.178: C17.2 R9.1 R13.1 R19.2 ; 53.34,47.5 53.31,47.52 53.31,47.66
  TOP w0.203: R19.2 53.34,47.64 53.34,46.18 53.44,46.08 53.44,45.54
UNNAMED_1_EKCONNSENSEPOINT_I310_P1: length 7.2
  TOP w0.178: Y12.1 55.4,38.77 55.4,37.3 55.3,37.2 55.3,32.99 J13.2
UNNAMED_1_EKCONNSENSEPOINT_I311_P1: length 7.2
  TOP w0.178: J13.1 55.85,33.1 55.85,38.77 Y15.1
UNNAMED_4_CAPNP_I188_1: length 10.7
  BOTTOM w0.381: SW1.5 SW1.2 31.85,12.7 32.46,13.31 C26.1 35.69,13.31 36.3,12.7 J6.2
UNNAMED_4_GT21MCBE_I190_3: length 2.5
  BOTTOM w0.381: SW1.6 SW1.3
UNNAMED_4_HEADER1PX2R_I239_1: length 9.4
  TOP w0.254: R17.1 56.64,15.21 J7.1
  L4_SIG w0.254: J7.1 TP6.1
UNNAMED_4_LED_I206_A: length 2.1
  TOP w0.254: DS1.A R51.2
UNNAMED_4_LED_I206_B: length 4.4
  TOP w0.254: DS1.K v1(31.57,18.9)
  BOTTOM w0.254: v1(31.57,18.9) 31.57,19.58 Q1.3
UNNAMED_4_RESSMD_I203_2: length 2.7
  BOTTOM w0.381: Q1.1 32.3,25.69 R42.2
VOUT: length 26
  L4_SIG w0.178: v1(70.66,46.61) 70.03,45.97 70.03,44.88 71.06,43.85 80.16,43.85 81.8,42.21 81.8,39.95 82.63,39.12 85.57,39.12 86.97,40.51 J19.1
  BOTTOM w0.254: v1(80.62,46.1) 80.37,45.85 C47.1 Y2.1
  vias: v1(68.3,24.64) v1(68.61,46.84) v1(68.71,37.08) v1(69.06,35.56) v1(69.24,46.84) v1(69.34,37.08) v1(69.32,31.75) v1(69.82,46.84) v1(69.93,37.08) v1(70.64,37.06) v1(71.22,19.56) v1(71.3,46.61) v1(71.27,37.06) v1(71.86,37.06) v1(71.88,46.61) v1(72.54,37.06) v1(72.57,46.61) v1(73.13,22.35) v1(73.25,54.1) v1(73.2,46.61) v1(73.18,37.06) v1(73.38,24.64) v1(73.76,57.15) v1(73.79,46.61) v1(73.76,37.06) v1(74.5,46.61) v1(74.47,37.06) v1(75.13,46.61) v1(75.11,37.06) v1(75.72,46.61) v1(75.69,37.06) v1(75.67,27.94) v1(76.35,46.61) v1(76.33,37.06) v1(76.3,35.18) v1(76.3,19.56) v1(76.99,46.61) v1(76.96,37.06) v1(77.57,46.61) v1(77.65,37.06) v1(78.08,50.42) v1(78.23,37.06) v1(78.21,22.35) v1(78.33,54.1) v1(78.28,46.61) v1(78.46,24.64) v1(78.59,16.38) v1(78.92,46.61) v1(78.87,37.06) v1(79.5,46.61) v1(79.5,37.06) v1(79.48,31.88) v1(79.48,13.08) v1(79.6,62.74) v1(79.86,28.07) v1(80.62,55.75) v1(81.38,19.56) v1(83.29,22.35) v1(83.54,24.64) v1(83.67,16.38) v1(84.05,6.86) v1(84.56,13.08) v1(84.68,62.74) v1(85.57,9.53) v1(86.46,19.56) v1(86.46,3.68) v1(87.1,53.85) v1(87.6,57.02) v1(87.86,70.99) v1(88.37,30.61) v1(88.37,22.35) v1(88.62,24.64) v1(88.75,16.38) v1(89.13,58.8) v1(89.13,6.86) v1(89.64,13.08) v1(89.76,62.74) v1(90.65,9.53) v1(91.54,59.31) v1(91.54,19.56) v1(91.54,3.68) v1(92.68,56.26) v1(93.45,22.35) v1(93.7,24.64) v1(93.83,16.38) v1(94.21,6.86) v1(94.72,13.08) v1(95.73,37.59) v1(95.73,9.53) v1(96.24,50.04) v1(96.37,46.23) v1(96.49,27.69) v1(96.62,19.56) v1(96.62,3.68) v1(97.76,56.26) v1(98.4,30.1) v1(98.91,37.85) v1(98.91,16.38) v1(99.42,46.48) v1(99.54,49.78) v1(99.8,13.08) v1(99.92,62.74) v1(100.81,9.53) v1(101.7,19.56) v1(102.72,73.66) v1(104.88,13.08) v1(105,62.74) v1(105.89,9.53) v1(106.15,67.18) v1(106.78,19.56) v1(107.67,16.38) v1(108.69,64.01) v1(108.81,46.1) v1(108.81,26.92) v1(108.81,12.83) v1(109.32,57.53) v1(110.97,9.53) v1(111.23,49.66) v1(111.61,30.1) v1(111.73,67.31) v1(111.73,14.73) v1(111.86,19.56) v1(111.99,60.58) v2(66.22,40.34) v2(66.27,43.69) v2(67.54,43.69) v2(67.59,40.34) v2(68.3,43.69) v2(68.4,40.34) v2(69.06,43.69) v2(69.22,40.34) v2(82.47,30.51) v2(83.11,30.51) v2(83.74,30.51) v2(84.38,30.51) v2(85.45,52.58) v2(86.08,52.58) v2(86.66,52.55) v2(87.35,52.55) v2(91.26,32.26) v2(91.72,50.34) v2(91.9,32.26) v2(92.53,32.26) v2(92.61,50.34) v2(93.17,32.26) v2(93.8,32.26)
VOUT_HF_CAP_N: length 67.7
  TOP w0.178: C17.1 R9.2 51.02,49.61 50.89,49.74 v1(50.89,50.57)
  L4_SIG w0.178: v3(53.51,43.86) 53.51,44 53.82,44.31 54.31,44.31 54.7,44.7 54.7,45.72
  L4_SIG w0.203: 54.7,45.72 54.7,46.62 53.09,48.23 53.09,50.04 52.56,50.57 v1(50.89,50.57)
  L4_SIG w0.254: v1(50.89,50.57) 50.89,51.25 51.89,52.25 51.89,55.58 55.74,59.42 79.26,59.42 84.79,53.9 84.79,45.63 83.36,44.21 82.16,44.21 v2(81.89,43.94)
  BOTTOM w0.254: v2(81.89,43.94) 81.81,43.87 Y1.2
VOUT_HF_CAP_P: length 101.4
  TOP w0.178: R14.2 v1(55.39,52.06)
  L3_SIG_AGND w0.178: TP14.1 32.17,70.23 31.28,71.12 31.28,71.82 31.91,72.45 40.81,72.45 42.2,71.06 42.2,68.27 42.23,68.24 42.23,67.77 47.25,62.75 55.59,62.75 57.69,60.65 57.69,52.51 57.25,52.06 v1(55.39,52.06)
  L4_SIG w0.254: v2(81.88,44.96) 82.13,44.7 83.16,44.7 84.29,45.83 84.29,53.69 79.06,58.93 55.95,58.93 52.45,55.43 52.45,52.43 52.81,52.06 v1(55.39,52.06)
  BOTTOM w0.254: Y2.2 81.56,44.88 81.64,44.96 v2(81.88,44.96)

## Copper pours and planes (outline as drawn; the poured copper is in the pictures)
1.8V_VCC on TOP: 54.97,43.69 55.35,43.69 55.63,43.94 55.96,43.94 56.46,44.45 56.87,44.83 58.39,44.83 59.16,45.47 59.16,46.23 56.11,46.23 56.11,44.96 55.73,44.96 54.84,44.07 54.84,43.82
AVDD on TOP: 55.98,48.01 55.09,48.01 55.09,47.37 55.07,47.35 55.07,45.64 54.41,45.64 54.41,44.2 54.58,44.2 55.12,44.73 55.35,44.73 55.91,45.29 55.91,46.41 55.98,46.48
GND_POWER on TOP: 70.43,43.69 70.43,39.93 79.86,39.93 79.86,43.69
GND_POWER on TOP: 65.76,35.81 65.76,21.84 86.59,1.02 0.74,1.14 0.74,42.67 16.1,42.65 51.92,42.65 52.03,42.53 53.01,42.53 53.01,42.18 53.01,41.53 53.01,41.18 53.01,40.53 54.51,40.53 55.01,40.53 55.34,40.53 55.34,39.46 55.2,39.32 55.18,36.01 55.37,35.81
GND_POWER on TOP: 44.35,52.78 35.28,62.1 0.74,62.1 0.74,75.44 44.3,75.49 84.25,75.44 65.38,50.83 65.38,46.43 50.65,46.43 ; 1 cut-out
GND_POWER on BOTTOM: 128.37,75.56 128.37,0.64 0.64,0.64 0.66,45.87 0.66,75.56
GND_POWER on L2_PGND: 0.66,75.56 128.37,75.56 128.37,0.64 0.64,0.64
GND_POWER on L5_PGND: 128.37,75.56 128.37,0.64 0.64,0.64 0.66,75.56
GND_SIGNAL on TOP: 54.15,44.27 53.97,44.27 53.67,44.58 53.7,46.74 53.7,47.12 53.95,47.37 53.95,48.01 54.84,48.01 54.84,47.5 54.71,47.37 54.71,45.72 54.33,45.72 54.33,44.45
GND_SIGNAL on L3_SIG_AGND: 45.69,60.33 57.25,60.33 57.25,52.07 54.71,49.53 54.71,47.24 57.12,44.83 57.12,43.94 45.69,43.94 ; 1 cut-out
VDDH on TOP: 0.74,61.85 35.15,61.85 52.81,44.32 52.81,43.82 52.93,43.66 54.71,43.66 54.71,43.18 0.74,43.18
VDDH on BOTTOM: 0.74,61.85 35.15,61.85 52.81,44.32 52.81,43.18 0.74,43.18
VDDH on L4_SIG: 0.74,61.85 35.15,61.85 52.81,44.32 52.81,43.18 0.74,43.18 ; 1 cut-out
LX on TOP: 54.87,43.03 57.12,43.03 57.12,43.94 58.78,43.94 59.79,44.96 62.03,44.93 62,36.35 55.6,36.32 55.6,40.68 55.01,40.68 55.01,42.03 54.87,42.68
UNNAMED_1_CAPNP_I293_2 on TOP: 56.97,44.15 56.36,44.15 56.03,43.82 55.35,43.82 54.89,43.36 54.89,43.18 56.97,43.18
VOUT on TOP: 84.43,75.44 128.24,75.44 128.24,0.76 87.29,0.76 66.07,22 66.04,38.74 65.71,39.07 65.68,50.88
VOUT on BOTTOM: 79.22,45.09 79.73,44.58 80.75,44.58 80.75,47.12 68.17,47.12 68.17,45.09
VOUT on BOTTOM: 85.19,49.66 85.19,52.81 87.73,52.81 87.73,49.66
VOUT on BOTTOM: 91.41,48.64 91.41,50.88 92.94,50.88 92.94,48.64
VOUT on BOTTOM: 79.76,38.35 79.76,36.75 68.28,36.75 68.28,38.35
VOUT on BOTTOM: 91.03,34.16 91.03,31.9 94.21,31.9 94.21,34.16
VOUT on BOTTOM: 82.14,33.4 82.14,30.07 84.68,30.07 84.68,33.4
VOUT on L3_SIG_AGND: 84.43,75.44 128.24,75.44 128.24,0.76 112.6,0.76 112.6,2.16 85.93,2.13 66.14,21.97 66.14,26.29 66.13,29.34 66.01,51.31 ; 3 cut-outs
VOUT on L4_SIG: 84.43,75.44 128.24,75.44 128.24,0.76 87.29,0.76 66.14,21.97 66.01,51.31 ; 7 cut-outs

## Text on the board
Ref Des/Silkscreen Top: PGND | LX | PGM2 | AVDD | AGND | PGM1 | CLK | DATA | GND | VIN_GND | EN | MAX16731_EVKIT_B | VOUT_GND | VOUT+
User.22: NOTES: | SURFACE FINISH: | TESTING: | SOLDERMASK: | MISCELLANEOUS: | SILKSCREEN: | MATERIAL: | TOOLING: | 16.  VENDOR LOGO & DATE CODE REQUIREMENT.  DATE CODE FORMAT MUST BE YYWW ONLY | 17.  FINAL ELECTRICAL TEST TO BE PERFORMED USING PROVIDED IPC-D-356A NETLIST OR ODB++ FORMAT FILE. | 18.  A TIME DOMAIN REFLECTOMETER REPORT FOR EACH IMPEDANCE CONTROLLED LAYER AND A CERTIFICATE | 19. IF PRESENT, ALL BLIND/BURIED VIAS WITH AN ASPECT RATIO <1:1 TO BE PLATED SHUT WITH COPPER WHEN | 20.  FOR ALL DRILL INFORMATION REFER TO DRILL CHART. | 21.  FINISHED SURFACE CONTACTS AND FILLED VIAS TO BE FREE OF ANY PITS. SCRATCHES PROBE MARKS | 23.  PEMNUT | 14.  SOLDERMASK OVER BARE COPPER OR BARE GOLD (BOTH SIDES) WITH LIQUID PHOTO IMAGEABLE (LPI) INK | 13.  DRILL SIZES ARE FINISHED HOLE SIZES. ALL HOLES SHALL BE LOCATED WITHIN .005 DTP,UNLESS SPECIFIED. | 22.  THIEVING: | 9.  ALL TRACES FILLETED OPTION TO ENHANCE RELIABILITY AT PAD JUNCTIONS | 10.  LAYER TO LAYER REGISTRATIONS SHALL BE WITHIN .003 INCHES. | 15. APPLY SILKSCREEN USING A NON-CONDUCTIVE EPOXY INK | 11.  FINISHED COPPER WEIGHT/THICKNESS: | 12. USE CHECKED ITEMS FOR PLATING | 3.  THE PCB SHALL BE FABRICATED TO IPC-6012, TYPE X, CLASS 2. | 4.  BOARD MATERIAL & CONSTRUCTION SHALL MEET THE REQUIREMENTS OF UL796 | 5.  OVERALL BOARD THICKNESS REFER TO LAMINATION DIAGRAM. TOLERANCE APPLIES | 6.  BOW & TWIST NOT TO EXCEED 0.0075 IN. (0.75%) PER LINEAR INCH. | 7.  PHOTO ETCH CIRCUITRY PER ENCLOSED GERBER RS274X OR ODB++ FORMAT FILE. | 8.  IMPEDANCE REQUIREMENTS: IF NO STACKUP IS DEFINED, THE VENDOR IS ALLOWED TO ADJUST THE DIELECTRIC | 1.  DIMENSIONS ARE IN INCHES (EXCEPT WHERE NOTED). | 2.  BOARD MATERIAL: | (X)  FINGERS TO BE GOLD PLATED. | (X)  FINISH CONDUCTOR SURFACES: IMMERSION GOLD, 1.58-3.94 MICRO INCHES OVER | (X)  WHITE | ( )  OTHER ________________________ | (X)  REFER TO LAMINATION DIAGRAM FOR FINISHED COPPER WEIGHT/THICKNESS REQUIREMENTS. | (X)  PLACE ON BOTTOM LEGEND LAYER. IF NO BOTTOM LEGEND SUPPLIED, CREATE BOTTOM LEGEND LAYER TO ADD. | ( )  PLACE ON TOP LEGEND LAYER. IF NO TOP LEGEND SUPPLIED,CREATE TOP LEGEND LAYER TO ADD. | ( )  ELECTRODEPOSITED HARD GOLD PLATE, TYPE 1 (99.7% MIN GOLD), GRADE C | (X)  CUSTOM MAXIM TEAL SOLDER MASK. PANTONE #326C. | MINIMUM BARREL PLATING OF .001 IN. PLATED HOLES SHALL NOT BE ROUGH OR IRREGULAR SO AS TO | HINDER PROPER SOLDER WICKING. BARREL RELIEF ON SOLDERMASK ALLOWED ON UNFILLED VIA IN PAD HOLES. | USED AS VIA-IN PAD OR AS A STACKED VIA. BLIND/BURIED VIAS WITH AN ASPECT RATIO >1:1 TO BE FILLED | WITH NON-CONDUCTIVE EPOXY. UNLESS OTHERWISE SPECIFIED. | (X)  NON-CONDUCTIVE EPOXY. FILL AND CAP ALL 0.005  INCH DRILLED VIAS. | ( )  SILVER. FILL AND CAP ALL 0.XXXX INCH DRILLED VIAS. | IF PRESENT,DO NOT MODIFY SOLDERMASK DEFINED PADS (MASK OPENINGS LESS THAN COPPER PAD) WITHOUT APPROVAL. | (REQUIRED UNLESS OTHERWISE SPECIFIED IN QUOTE) | THE PCB SHALL HAVE A VERIFICATION STAMP. | OR OTHER DEFORMITIES THAT COULD EFFECT THE APPERANCE AND PERFORMACE OF THE CONTACT | SURFACE. CONTACTS ARE TO BE AS FLAT AS POSSIBLE. NOT TO EXCEED +/- 0.001" OF FLATNESS. | OF COMPLIANCE SHALL BE PROVIDED BY VENDOR AT TIME OF SHIPMENT. INSTANCES WHERE TDR TESTING | CAN'T BE PERFORMED BECAUSE THE TRACE LENGTH IS TOO SHORT ON THE OUTER LAYERS AT THE PIN ESCAPES | IS ACCEPTABLE, ALL OTHER INSTANCES MUST BE REPORTED. | ( )  SUPPLIER MAY ADD THIEVING TO COMPENSATE FOR LOW COPPER DENSITY AREAS ON THIS DESIGN. | WHERE SPACING PERMITS. | LEGEND TO LEGEND +/- 0.007 INCHES | (X)  SUPPLIER MAY NOT ADD THIEVING TO COMPENSATE FOR LOW COPPER DENSITY AREAS ON THIS DESIGN. | ( )  PEMNUTS TO BE INSTALLED BY FABRICATOR.. | ( )  PEMNUTS NOT TO BE INSTALLED BY FABRICATOR. | (X)  NOT APPLICABLE. | ( )  FILLETED | (X)  NOT FILLETED | (X)  ISOLA 370HR OR EQUIVALENT | ( )  NELCO-4000-13 | ( )  MEGTRON 6 | ( )  ROGERS 4350B | ( )  ROGERS 4003C | ( )  ISOLA-FR408HR OR EQUIVALENT | WORKMANSHIP SHALL CONFORM TO IPC-A-600, CLASS 2, CURRENT REVISIONS. | WITH FLAMMABILITY RATING OF 94V-O. | AFTER ALL LAMINATION AND PLATING PROCESSES. IT IS TO BE MEASURED FROM | TOP PCB METAL TO BOTTOM PCB METAL UNLESS OTHERWISE SPECIFIED. | BOW & TWIST SHOULD BE MEASURED PER IPC-TM-650, METHOD 2.4.22. | DRILL LOCATION AND SIZE CONTROLLED BY EXCELLON CNC DRILL FILE. | THICKNESS AND TRACE WIDTHS TO MEET THE IMPEDANCE REQUIREMENT. IF SPECIFIED, VENDOR MUST FOLLOW AND | MEET THE REQUIREMENTS LISTED IN THE IMPEDANCE TABLE. ANY ADJUSTMENTS MADE TO THE DEFINED STACKUP, | TRACE WIDTH & SPACING THAT IMPACT THE REQUIREMENTS MUST HAVE WRITTEN APPROVAL FROM MAXIM. | UNLESS OTHERWISE SPECIFIED | (USE CHECKED ITEMS FOR MATERIAL) | (KNOOP HARDNESS 130-200), CLASS 1 (50-100 MICRO INCHES THICK) IN ACCORDANCE WITH MIL-G-45204C. | GENERAL SURFACING REQUIREMENTS MUST MEET ANSI/IPC-A-600(CURRENT REV) SECTION 4.0, | CLASS 3 (50-100 MICROINCHES THICK) OVER ELECTRODEPOSITED NICKEL PLATE | IN ACCORDANCE WITH ANSI/IPC-A-600D, SECTION 4.0, CLASS 3 (200-600 MICROINCHES THICK). | 118-236 MICRO INCHES MINIMUM OF ELECTROLESS NICKEL. | THE STARTING COPPER WEIGHT/THICKNESS CAN VARY AS LONG AS THE FINISHED COPPER | WEIGHT/THICKNESS IS NOT LESS THAN THE SPECIFIED VALUE, UNLESS OTHERWISE SPECIFIED. | UNLESS OTHERWISE SPECIFIED: | MAX16731_EVKIT_B
User.26: FIGURE | SIZE | 5.0 | 8.0 | 10.0 | 35.43 | 45.28 | 62.99 | 102.36 | 270.0 | 187.01 | TOLERANCE | +3.0/-3.0 | +3.0/-6.0 | +3.0/-8.0 | PLATED | NON-PLATED | ALL UNITS ARE IN MILS | QTY | 5 | 470 | 172 | 6 | 23 | 12 | 2 | 4 | NOTES | DRILL CHART: TOP to BOTTOM
